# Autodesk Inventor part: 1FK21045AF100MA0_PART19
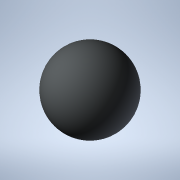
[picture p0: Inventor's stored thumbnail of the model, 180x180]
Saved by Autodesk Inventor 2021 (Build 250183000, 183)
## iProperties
Created: 2025-04
Part Number: 1FK21045AF100MA0_PART19
Material: Generic
Catalog Web Link: www.3dfindit.com
Description: -Servo synchronous motor
Document SubType Name: Modeling
Designer: psAdmin
Mass: 0.137258 g
Surface Area: 1.2868 cm^2
Volume: 0.137258 cm^3
Density: 1 g/cm^3
Appearance: PSOLRGB-212-217-219
Category: PARTsolutions
Title: 1FK21045AF100MA0_PART19
Author: Cadenas PARTsolutions
Comments: Servo synchronous motor
Sending System: PARTsolutions
Preprocessor: ST-DEVELOPER v19.3
PSOL_IDENT_0: {$CADENAS_DATA/23d-libs/siemens_ag/_cat_/52/6b/1fk21045af100ma0.prj},216 {VTYP=3D},{NB=1FK21045AF100
PSOL_IDENT_1: MA0_PART19},{LINA=1FK21045AF100MA0_PART19},{NN=1FK21045AF100MA0_PART19},{NOPRJ=TRUE},{DATE=19.08.202
PSOL_IDENT_2: 5 14:00:38},{GEOMDATE=30.07.2025 02:01:45},{VERSION=},{LINEID=10},{WBVAR=},{WBNUMERIC=}  {NB=1FK2104
PSOL_IDENT_3: 5AF100MA0_PART19},{LINA=1FK21045AF100MA0_PART19},{KT=DUMMY},{PREVIEW=../../../_pool_/cb/72/p_d211_xx
PSOL_IDENT_4: _00434j.png},{DESCSHORT=SIMOTICS S-1FK2 HD, SINAMICS S210 3AC 400V-480V, 2.4 Nm, 3000 rpm},{DESCLONG=
PSOL_IDENT_5: SIMOTICS S-1FK2 HD servo motor M0=2.4 Nm; PN = 0.75 kW at nN=3000 rpm (380-480 V); PN = 0.375 kW at
PSOL_IDENT_6: nN=1500 rpm (200-240 V); with holding brake; degree of protection IP64; cylindrical shaft D19x40mm;
PSOL_IDENT_7: absolute encoder 22-bit + 12-bit multiturn (encoder AM22DQC); with OCC interface; plug size M17, rot
PSOL_IDENT_8: atable; SIMOTICS S-1FK2 servomotorfor a wide range of uses in industrial environments. SIMOTICS S‑1F
PSOL_IDENT_9: K2 servomotors are compact synchronous motors with a high dynamic performance that set themselves ap
PSOL_IDENT_10: art as a result of their high power density, degree of protection and overload capability. The motor
PSOL_IDENT_11: s are available in two variants: as High Dynamic variant (highest dynamic performance as a result of
PSOL_IDENT_12: the low intrinsic moment of inertia for applications demanding a high dynamic performance with low
PSOL_IDENT_13: moved masses) - and as Compact variant (precise and stable closed-loop control for medium up to larg
PSOL_IDENT_14: e moved masses as a result of a medium intrinsic moment of inertia). SIMOTICSS‑1FK2 servomotors full
PSOL_IDENT_15: y exploit their strengths in a system with the SINAMICSS210 frequency converter and simple connectio
PSOL_IDENT_16: n using the one cable connection (OCC). Advantages include the short control and positioning times,
PSOL_IDENT_17: fast and precise correction of disturbing quantities as well as stable control with a high dynamic p
PSOL_IDENT_18: erformance. The servo motors can be configured to address a wide range of requirements. For example
PSOL_IDENT_19: with and without holding brake, IP64 or IP65 degree of protection, singleturn or multiturn absolute
PSOL_IDENT_20: encoders - to name just a few. Further, the servomotors are available in different shaft heights ext
PSOL_IDENT_21: ending from 20 to 100. A shaft sealing ring is available to achieve an IP65 degree of protection and
PSOL_IDENT_22: for subsequent mounting at the motor or as spare part. SIMOTICS - the optimum motor for each and ev
PSOL_IDENT_23: ery motion control application.},{INTNO=804766906411},{SUPPLIERALTNO=1FK2104-5AF10-0MA0},{MANUID=1FK
PSOL_IDENT_24: 21045AF100MA0},{MANUNAME=Siemens},{MANUTYPEDESC=Synchronous motor 1FK2-HD 2.4 NM},{AAU732=SIMOTICS},
PSOL_IDENT_25: {AAO057=S-1FK2},{AAU734=SIMOTICS S-1FK2 HD servo motor M0=2.4 Nm; PN = 0.75 kW at nN=3000 rpm (380-4
PSOL_IDENT_26: 80 V); PN = 0.375 kW at nN=1500 rpm (200-240 V); with holding brake; degree of protection IP64; cyli
PSOL_IDENT_27: ndrical shaft D19x40mm; absolute encoder 22-bit + 12-bit multiturn (encoder AM22DQC); with OCC inter
PSOL_IDENT_28: face; plug size M17, rotatable;},{AAW338=Synchronous motor 1FK2-HD 2.4 NM},{AAO742=SIMOTICS},{AAO663=
PSOL_IDENT_29: 4042948693070},{NOCUPEROU=1},{PRICEQUANTITY=1},{QUANTITYMIN=1},{QUANTITYINT=1},{CTN=85015100},{COO=D
PSOL_IDENT_30: E},{AAO676=1FK2104-5AF10-0MA0},{AAO677=Siemens AG},{ORDERUNIT=C62},{CONTENTUNIT=C62}
NB: 1FK21045AF100MA0_PART19
NT: Servo synchronous motor
NBSYN: $MANUID._PART19
LINA: 1FK21045AF100MA0_PART19
CATALOG: SIEMENS
PREVIEW: ../../../_pool_/cb/72/p_d211_xx_00434j.png
DESCSHORT: SIMOTICS S-1FK2 HD, SINAMICS S210 3AC 400V-480V, 2.4 Nm, 3000 rpm
DESCLONG: SIMOTICS S-1FK2 HD servo motor M0=2.4 Nm; PN = 0.75 kW at nN=3000 rpm (380-480 V); PN = 0.375 kW at nN=1500 rpm (200-240 V); with holding brake; degree of prote
INTNO: 804766906411
SUPPLIERALTNO: 1FK2104-5AF10-0MA0
MANUID: 1FK21045AF100MA0
MANUNAME: Siemens
MANUTYPEDESC: Synchronous motor 1FK2-HD 2.4 NM
AAU732: SIMOTICS
AAO057: S-1FK2
AAU734: SIMOTICS S-1FK2 HD servo motor M0=2.4 Nm; PN = 0.75 kW at nN=3000 rpm (380-480 V); PN = 0.375 kW at nN=1500 rpm (200-240 V); with holding brake; degree of prote
AAW338: Synchronous motor 1FK2-HD 2.4 NM
AAO742: SIMOTICS
AAO663: 4042948693070.0
NOCUPEROU: 1
PRICEQUANTITY: 1
QUANTITYMIN: 1
QUANTITYINT: 1
CTN: 85015100
COO: DE
ARTICLENO: 1FK21045AF100MA0_PART19
BOMINFO: 1FK21045AF100MA0_PART19
CREATOR: CADENAS GmbH
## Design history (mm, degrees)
feature "2025_04_17_15_34_52_0317"
body "Solid1"
